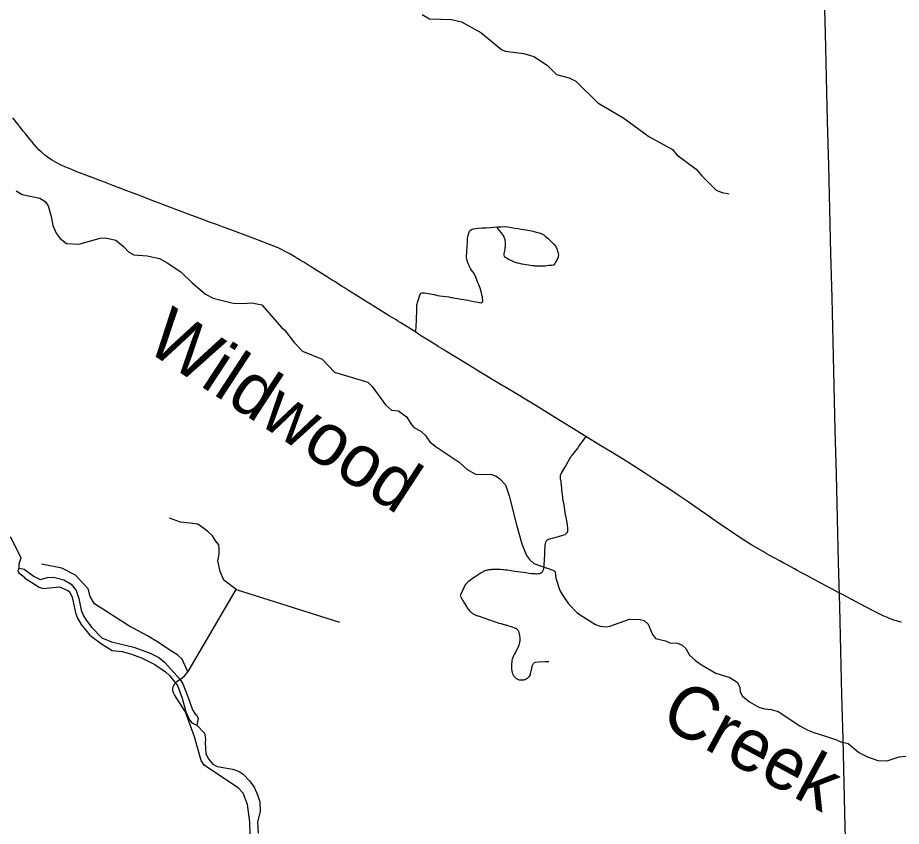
# Model space of a CAD drawing. Extents: x -19 to 366, y -4 to 359.
# Drawn here: x 140.926 to 142.275, y 192.835 to 194.069 of the extents above; entities that cross this region are included whole.
import ezdxf

# ---------------------------------------------------------------- set-up
doc = ezdxf.new("R2010")
doc.units = 0
for name, color, linetype in [('R_ROW', 7, 'Continuous'), ('R_ROW Annot', 7, 'Continuous'), ('R_Striping', 7, 'Continuous'), ('R_Temp Easement', 7, 'Continuous'), ('Sheet Fence', 7, 'Continuous')]:
    doc.layers.add(name, color=color, linetype=linetype)

msp = doc.modelspace()

# ---------------------------------------------------------------- linework, layer by layer
at = {"layer": 'R_ROW'}
for points in [[(141.5338, 193.589), (141.5108, 193.6034), (141.5066, 193.606), (141.5037, 193.6078), (141.4931, 193.6143), (141.4893, 193.6166), (141.4689, 193.6294), (141.4657, 193.6313), (141.4598, 193.635), (141.4564, 193.6372), (141.431, 193.653), (141.425, 193.6568), (141.4216, 193.659), (141.4142, 193.6637), (141.41, 193.6663), (141.4052, 193.6692), (141.3977, 193.674), (141.3895, 193.6791), (141.3827, 193.6834), (141.3772, 193.6868), (141.3739, 193.689), (141.3705, 193.6911), (141.3677, 193.6929), (141.3627, 193.6959), (141.3579, 193.6988), (141.3542, 193.701), (141.3505, 193.7033), (141.3455, 193.7063), (141.3442, 193.707), (141.3414, 193.7086), (141.3397, 193.7096), (141.3239, 193.7177), (141.3106, 193.7231), (141.2988, 193.7277), (141.2879, 193.7318), (141.2841, 193.7331), (141.2772, 193.7357), (141.2555, 193.7438), (141.2471, 193.7469), (141.2388, 193.7499), (141.2308, 193.7529), (141.2174, 193.7578), (141.2113, 193.76), (141.2031, 193.7632), (141.1935, 193.7667), (141.1862, 193.7695), (141.1788, 193.7723), (141.1701, 193.7756), (141.1622, 193.7785), (141.1484, 193.7836), (141.1408, 193.7866), (141.1337, 193.7893), (141.1271, 193.7918), (141.1183, 193.7952), (141.0995, 193.8024), (141.0912, 193.8056), (141.0847, 193.8081), (141.0777, 193.8107), (141.071, 193.8133), (141.0633, 193.8163), (141.056, 193.819), (141.0497, 193.8214), (141.0436, 193.8237), (141.0259, 193.8304), (141.0189, 193.8331), (141.0033, 193.8393), (140.9978, 193.8417), (140.9915, 193.8445), (140.9857, 193.8475), (140.9775, 193.8521), (140.9708, 193.8566), (140.9673, 193.8593), (140.9621, 193.8638), (140.9584, 193.8676), (140.9545, 193.8716), (140.951, 193.8757), (140.9474, 193.88), (140.9423, 193.8862), (140.9381, 193.8913), (140.9342, 193.8961), (140.9311, 193.9001), (140.9284, 193.9035), (140.9259, 193.9067), (140.9185, 193.9166)], [(141.7937, 193.4299), (141.7845, 193.4355), (141.7788, 193.439), (141.754, 193.4543), (141.747, 193.4586), (141.7145, 193.4786), (141.6984, 193.4884), (141.6927, 193.4919), (141.6696, 193.5058), (141.6668, 193.5074), (141.6271, 193.5314), (141.6224, 193.5343), (141.6014, 193.5469), (141.5965, 193.5499), (141.5797, 193.5602), (141.575, 193.5631), (141.5678, 193.5675), (141.5628, 193.5707), (141.5428, 193.5833), (141.5382, 193.5862), (141.5338, 193.589)], [(141.7937, 193.4299), (141.7835, 193.416), (141.7811, 193.4128), (141.773, 193.4024), (141.7715, 193.4004), (141.7708, 193.3996), (141.77, 193.3985), (141.7691, 193.3971), (141.7685, 193.3959), (141.763, 193.3856), (141.7612, 193.3825), (141.756, 193.3738), (141.7555, 193.3727), (141.755, 193.3718), (141.7546, 193.3703), (141.7544, 193.3689), (141.7543, 193.3671), (141.7545, 193.3654), (141.755, 193.3636), (141.7553, 193.3611), (141.7559, 193.3545), (141.7562, 193.3521), (141.7564, 193.3496), (141.7566, 193.3482), (141.7578, 193.3377), (141.758, 193.3357), (141.7586, 193.3322), (141.7592, 193.3289), (141.7622, 193.3105), (141.7628, 193.3072), (141.7648, 193.2946), (141.7654, 193.2907), (141.7655, 193.2895), (141.7657, 193.2869), (141.7655, 193.2851), (141.7645, 193.2832), (141.7639, 193.2825), (141.7613, 193.2801), (141.7578, 193.2789), (141.7511, 193.2766), (141.7478, 193.2757), (141.746, 193.2752), (141.7438, 193.2746), (141.7422, 193.2741), (141.7403, 193.2737), (141.7378, 193.2731), (141.7359, 193.2724), (141.7346, 193.2716), (141.7337, 193.2708), (141.7329, 193.2699), (141.7322, 193.2686), (141.7315, 193.2666), (141.7311, 193.2639), (141.7308, 193.2611), (141.7305, 193.2565), (141.7303, 193.2534), (141.7302, 193.2503), (141.7296, 193.2338), (141.7295, 193.2322), (141.7294, 193.2309), (141.7291, 193.2289), (141.7287, 193.2274), (141.7281, 193.2254), (141.7276, 193.2241), (141.727, 193.2231), (141.7263, 193.2222), (141.7259, 193.2219), (141.7243, 193.2211), (141.7229, 193.2206), (141.7206, 193.2201), (141.7187, 193.22), (141.7175, 193.22), (141.716, 193.2201), (141.7125, 193.2203), (141.7105, 193.2206), (141.7066, 193.221), (141.7018, 193.2217), (141.6899, 193.2233), (141.6852, 193.2239), (141.6738, 193.2258), (141.6722, 193.226), (141.6708, 193.2262), (141.6681, 193.2264), (141.6666, 193.2266), (141.6629, 193.2268), (141.6607, 193.2269), (141.6597, 193.2269), (141.6579, 193.2269), (141.6496, 193.2268), (141.6484, 193.2267), (141.6458, 193.2265), (141.6448, 193.2264), (141.6441, 193.2262), (141.6425, 193.2259), (141.6417, 193.2256), (141.6392, 193.2247), (141.6378, 193.224), (141.636, 193.223), (141.6346, 193.2222), (141.6338, 193.2218)], [(142.1056, 193.2313), (142.1009, 193.2339), (142.0957, 193.2368), (142.0897, 193.24), (142.08, 193.2455), (142.0746, 193.2485), (142.0692, 193.2515), (142.0677, 193.2523), (142.0587, 193.2574), (142.0473, 193.264), (142.0287, 193.2756), (142.0173, 193.2832), (141.9941, 193.2993), (141.9821, 193.3077), (141.97, 193.3162), (141.9498, 193.3301), (141.9348, 193.3402), (141.9227, 193.3484), (141.9118, 193.3555), (141.9, 193.3633), (141.891, 193.3693), (141.8845, 193.3735), (141.8705, 193.3826), (141.8519, 193.3943), (141.8311, 193.407), (141.8166, 193.4159), (141.7937, 193.4299)], [(141.2596, 193.1963), (141.2407, 193.2106), (141.2349, 193.224), (141.2317, 193.24), (141.2336, 193.2509), (141.2336, 193.2586), (141.233, 193.2644), (141.2285, 193.2702), (141.2234, 193.2785), (141.2157, 193.2855), (141.201, 193.2964), (141.1895, 193.2977), (141.1747, 193.299), (141.1575, 193.3054)], [(142.1662, 193.199), (142.1613, 193.2016), (142.1547, 193.2051), (142.1302, 193.2182), (142.1219, 193.2226), (142.1163, 193.2256), (142.112, 193.2279), (142.1056, 193.2313)], [(141.6338, 193.2218), (141.6323, 193.2208), (141.6243, 193.2156), (141.6205, 193.2131), (141.6199, 193.2126), (141.618, 193.2112), (141.6139, 193.2082), (141.6127, 193.2072), (141.6122, 193.2067), (141.6113, 193.2057), (141.6107, 193.205), (141.6099, 193.2039), (141.609, 193.2024), (141.6071, 193.1989), (141.6064, 193.1976), (141.6057, 193.1961), (141.6019, 193.1883), (141.6015, 193.1874)], [(142.2466, 193.1568), (142.2435, 193.1584), (142.2387, 193.1608), (142.2178, 193.1716), (142.2159, 193.1727), (142.2025, 193.1798), (142.1996, 193.1813), (142.1846, 193.1892), (142.1812, 193.191), (142.1709, 193.1965), (142.1662, 193.199)], [(141.1858, 193.071), (141.1878, 193.074), (141.2596, 193.1963), (141.4174, 193.1466)], [(141.6015, 193.1874), (141.6054, 193.1801), (141.6063, 193.1785), (141.6069, 193.1775), (141.6113, 193.1703), (141.6135, 193.1668), (141.6143, 193.1659), (141.6164, 193.1635), (141.617, 193.1629), (141.6175, 193.1623), (141.6183, 193.1617), (141.6207, 193.1599), (141.6217, 193.1593), (141.6224, 193.1589), (141.6233, 193.1585), (141.6248, 193.1578), (141.6282, 193.1564), (141.629, 193.1561), (141.648, 193.1494), (141.6506, 193.1485), (141.6582, 193.146), (141.6609, 193.1452), (141.6643, 193.1443), (141.6664, 193.1437), (141.6674, 193.1435), (141.6703, 193.1427), (141.6717, 193.1423), (141.6755, 193.1411), (141.6796, 193.1398), (141.6812, 193.1393), (141.6834, 193.1385), (141.6858, 193.1376), (141.6864, 193.1373), (141.6868, 193.1372), (141.6874, 193.1367), (141.6889, 193.1354), (141.6894, 193.1348), (141.6902, 193.1337), (141.6907, 193.1326), (141.6912, 193.1307), (141.6917, 193.1289), (141.6922, 193.1262), (141.6925, 193.1251), (141.6927, 193.1231), (141.6928, 193.1219), (141.6926, 193.1172), (141.6925, 193.1168), (141.6923, 193.1155), (141.6919, 193.1133), (141.6914, 193.1117), (141.6903, 193.1089), (141.6901, 193.1083), (141.6891, 193.1064), (141.6857, 193.1), (141.6848, 193.0981), (141.6833, 193.0952), (141.6827, 193.0938), (141.6818, 193.0918), (141.6812, 193.0902), (141.6807, 193.0882), (141.6805, 193.0869), (141.6803, 193.0855), (141.68, 193.083), (141.6799, 193.081), (141.6798, 193.0797), (141.6798, 193.078), (141.68, 193.0762), (141.6801, 193.0742), (141.6805, 193.0723), (141.6811, 193.0699), (141.6814, 193.0686), (141.6822, 193.0668), (141.6828, 193.0656), (141.6832, 193.0649), (141.6844, 193.0633), (141.6855, 193.0621), (141.6863, 193.0614), (141.6874, 193.0605), (141.6885, 193.06), (141.6893, 193.0596), (141.69, 193.0593), (141.6908, 193.0591), (141.6919, 193.0588), (141.6929, 193.0586), (141.6936, 193.0585), (141.6956, 193.0584), (141.6961, 193.0584), (141.6968, 193.0584), (141.6973, 193.0585), (141.6995, 193.0588), (141.7001, 193.059), (141.7008, 193.0592), (141.7016, 193.0595), (141.7028, 193.0601), (141.7035, 193.0605), (141.7043, 193.061), (141.7046, 193.0612), (141.705, 193.0615), (141.7066, 193.0631), (141.7069, 193.0634)], [(142.2728, 193.1473), (142.2684, 193.1484), (142.2656, 193.1492), (142.2582, 193.1518), (142.2541, 193.1535), (142.2489, 193.1558), (142.2466, 193.1568)], [(141.7069, 193.0634), (141.7073, 193.0638), (141.7078, 193.0646), (141.7089, 193.0664), (141.709, 193.0666), (141.7093, 193.0679), (141.7102, 193.0724), (141.7104, 193.0735), (141.7112, 193.077), (141.7115, 193.0782), (141.7122, 193.0808), (141.7127, 193.0818), (141.7132, 193.0827), (141.7135, 193.0834), (141.7145, 193.0843), (141.7152, 193.0849), (141.7154, 193.085), (141.7173, 193.0857), (141.7214, 193.086), (141.7317, 193.0864), (141.7334, 193.0864), (141.737, 193.0865)], [(141.2824, 192.761), (141.2805, 192.842), (141.277, 192.8681), (141.27, 192.8857), (141.2626, 192.8938), (141.2311, 192.9144), (141.2108, 192.9281), (141.2061, 192.9356), (141.1959, 192.9716), (141.1831, 193.0069), (141.1806, 193.0117), (141.1653, 193.0356), (141.1641, 193.0378), (141.1633, 193.0402), (141.1629, 193.0427), (141.163, 193.0452), (141.1634, 193.0477), (141.1643, 193.0501), (141.1655, 193.0523), (141.1671, 193.0542), (141.169, 193.0559), (141.1725, 193.0584), (141.1769, 193.0615), (141.1811, 193.0652), (141.1847, 193.0693), (141.1858, 193.071)]]:
    msp.add_lwpolyline(points, dxfattribs=at)
at = {"layer": 'R_ROW Annot'}
for points in [[(141.5338, 193.589), (141.5345, 193.5992), (141.5346, 193.6004), (141.535, 193.6056), (141.5351, 193.6077), (141.5352, 193.609), (141.5354, 193.6223), (141.5354, 193.629), (141.5354, 193.6303), (141.5358, 193.6318), (141.5364, 193.6341), (141.537, 193.6363), (141.5378, 193.6389), (141.54, 193.6459), (141.5409, 193.648), (141.5434, 193.6492), (141.5471, 193.6494), (141.5619, 193.6468), (141.5669, 193.6454), (141.5708, 193.6445), (141.5845, 193.6431), (141.5877, 193.6423), (141.5901, 193.6419), (141.5942, 193.6413), (141.5979, 193.6408), (141.6032, 193.6398), (141.6074, 193.6391), (141.6131, 193.638), (141.6223, 193.6361), (141.6257, 193.6354), (141.6281, 193.635), (141.6311, 193.6344), (141.6339, 193.634), (141.6362, 193.6358), (141.6355, 193.6434), (141.6353, 193.6444), (141.6344, 193.6491), (141.632, 193.6564), (141.631, 193.6589), (141.63, 193.6613), (141.6295, 193.6627), (141.6287, 193.6645), (141.6276, 193.6675), (141.6254, 193.6734), (141.6246, 193.6756), (141.6237, 193.6774), (141.6233, 193.678), (141.6192, 193.6836), (141.6174, 193.6865), (141.6155, 193.6903), (141.615, 193.6912), (141.6147, 193.6922), (141.614, 193.6939), (141.6125, 193.6982), (141.6121, 193.6994), (141.6117, 193.7007), (141.6114, 193.7032), (141.6113, 193.7049), (141.6113, 193.7058), (141.6117, 193.7104), (141.6119, 193.7132), (141.6122, 193.7194), (141.6126, 193.7267), (141.6129, 193.7308), (141.6134, 193.7356), (141.6137, 193.7368), (141.6147, 193.7401), (141.6161, 193.7433), (141.6175, 193.745), (141.6189, 193.746), (141.6219, 193.7469), (141.6249, 193.7475), (141.6293, 193.7481), (141.635, 193.7484), (141.6415, 193.7487), (141.6479, 193.7492), (141.6531, 193.7494), (141.6585, 193.7498)], [(141.6585, 193.7498), (141.6642, 193.7502), (141.6693, 193.7503), (141.6742, 193.7499), (141.6801, 193.7489), (141.6845, 193.7479), (141.6902, 193.7472), (141.6948, 193.7466), (141.7021, 193.7455), (141.7078, 193.7445), (141.7128, 193.7434), (141.7177, 193.7421), (141.7223, 193.7407), (141.7265, 193.7394), (141.7293, 193.7379), (141.7317, 193.7358), (141.7359, 193.732), (141.7407, 193.7274), (141.7447, 193.7236), (141.7471, 193.7207), (141.7478, 193.7197), (141.7486, 193.7179), (141.7499, 193.7147), (141.7505, 193.713), (141.7512, 193.7101), (141.7516, 193.7075), (141.7513, 193.7052), (141.7511, 193.7038), (141.7498, 193.7003), (141.7474, 193.6961), (141.7461, 193.6941), (141.7446, 193.692), (141.7435, 193.6914), (141.741, 193.6912), (141.7385, 193.691), (141.7365, 193.6908), (141.7342, 193.6905), (141.7321, 193.6902), (141.7292, 193.6899), (141.7263, 193.6898), (141.722, 193.6897), (141.7199, 193.6899), (141.7163, 193.6902), (141.715, 193.6904), (141.7122, 193.6907), (141.7083, 193.6912), (141.7058, 193.6916), (141.7026, 193.6921), (141.6996, 193.6926), (141.6959, 193.6932), (141.6927, 193.6938), (141.6892, 193.6947), (141.6847, 193.6963), (141.6818, 193.6975), (141.6796, 193.6984), (141.6765, 193.6998), (141.6747, 193.7007), (141.6725, 193.7021), (141.671, 193.7031), (141.67, 193.7039), (141.6693, 193.7048), (141.6689, 193.7065), (141.6689, 193.7077), (141.669, 193.7092), (141.6695, 193.7115), (141.6699, 193.7136), (141.6702, 193.7153), (141.6705, 193.7174), (141.6706, 193.7184), (141.6707, 193.7191), (141.6707, 193.7252), (141.6703, 193.7299), (141.6695, 193.7329), (141.6683, 193.7359), (141.665, 193.7409), (141.6614, 193.7451), (141.6598, 193.7471), (141.6589, 193.7484), (141.6585, 193.7498)], [(141.1858, 193.071), (141.1773, 193.09), (141.1705, 193.0964), (141.1567, 193.1048), (141.141, 193.1153), (141.1241, 193.1255), (141.0954, 193.1411), (141.0434, 193.1748), (141.0365, 193.186), (141.0336, 193.1973), (141.014, 193.2183), (140.9935, 193.2292), (140.9622, 193.2349)]]:
    msp.add_lwpolyline(points, dxfattribs=at)
at = {"layer": 'R_Striping'}
msp.add_lwpolyline([(142.2759, 193.1466), (142.2728, 193.1473)], dxfattribs=at)
at = {"layer": 'R_Temp Easement'}
for points in [[(141.5435, 194.0741), (141.5549, 194.0674), (141.5886, 194.0667), (141.6038, 194.0627), (141.6331, 194.0464), (141.6648, 194.0206), (141.6705, 194.018), (141.6989, 194.0146), (141.7141, 194.0099), (141.7347, 193.9968), (141.7489, 193.9826), (141.7682, 193.9772), (141.7781, 193.9723), (141.8118, 193.9394), (141.8514, 193.9156), (141.8896, 193.888), (141.9258, 193.868), (141.9323, 193.8601), (141.9621, 193.8381), (141.9709, 193.8279), (141.9924, 193.8062), (142.0019, 193.8025), (142.0125, 193.8004)], [(140.9233, 193.8051), (140.9328, 193.7992), (140.9597, 193.7936), (140.9678, 193.7888), (140.9724, 193.782), (140.9772, 193.7658), (140.9797, 193.7518), (140.9848, 193.7405), (140.9907, 193.7322), (141.0002, 193.7244), (141.0195, 193.7236), (141.0519, 193.7325), (141.0602, 193.7334), (141.0757, 193.7295), (141.0876, 193.7198), (141.0949, 193.712)], [(141.0949, 193.712), (141.1033, 193.7072), (141.1234, 193.7057), (141.1423, 193.7014), (141.1542, 193.6952), (141.1752, 193.6811), (141.1925, 193.6647), (141.2128, 193.6472), (141.2243, 193.641), (141.255, 193.6335), (141.269, 193.633), (141.2833, 193.634), (141.2985, 193.6308), (141.329, 193.5965), (141.3336, 193.5927), (141.3479, 193.5736), (141.3606, 193.5602), (141.391, 193.5478), (141.4095, 193.528), (141.4608, 193.5129), (141.4673, 193.5062), (141.4875, 193.4781), (141.497, 193.4703), (141.5076, 193.469), (141.5199, 193.4601), (141.5281, 193.4469), (141.5311, 193.4436), (141.5414, 193.438), (141.5487, 193.4317), (141.5553, 193.422), (141.5634, 193.4153), (141.6001, 193.3908), (141.6124, 193.3797), (141.625, 193.3723), (141.6386, 193.3718), (141.6484, 193.3727), (141.6568, 193.3694), (141.6621, 193.3653), (141.671, 193.356), (141.6765, 193.3394), (141.6879, 193.2952), (141.6956, 193.2661), (141.7031, 193.2484), (141.7073, 193.2424), (141.7139, 193.2361), (141.7447, 193.2252), (141.7466, 193.2233), (141.7479, 193.2135), (141.7539, 193.195), (141.7582, 193.1871), (141.7671, 193.1744), (141.7806, 193.1605), (141.8085, 193.1428), (141.8157, 193.1403), (141.8248, 193.1397), (141.8304, 193.1405), (141.8601, 193.1513), (141.8763, 193.1508), (141.8828, 193.149), (141.8889, 193.1434), (141.8953, 193.128)], [(140.9143, 193.2774), (140.9299, 193.2475), (140.9307, 193.2441), (140.9277, 193.2353), (140.9277, 193.2289), (140.9262, 193.2251)], [(140.9277, 193.2289), (140.9357, 193.2274), (140.9512, 193.2161), (140.9603, 193.2119), (140.9716, 193.215), (140.9807, 193.2151), (140.9966, 193.2113), (141.0076, 193.2045), (141.0152, 193.1951), (141.0194, 193.1826), (141.0229, 193.1648), (141.0263, 193.1564), (141.0305, 193.1496), (141.0389, 193.1386), (141.0544, 193.1228), (141.0692, 193.1164), (141.1033, 193.1082), (141.1283, 193.0995), (141.1412, 193.0924), (141.1503, 193.0856), (141.1742, 193.0591), (141.178, 193.0527), (141.186, 193.0315), (141.1929, 193.0129), (141.1975, 193.0057), (141.199, 193.005), (141.2017, 192.9997), (141.1994, 192.9894)], [(140.9262, 193.2251), (140.927, 193.2224), (140.9361, 193.2153), (140.9361, 193.2141), (140.9585, 193.1998), (140.9649, 193.1979), (140.9895, 193.2003), (141.0023, 193.195), (141.0054, 193.1924), (141.0092, 193.1848), (141.0142, 193.1606), (141.0173, 193.1526), (141.0226, 193.1428), (141.0363, 193.1265), (141.0537, 193.1133), (141.0704, 193.1035), (141.0855, 193.1016), (141.0984, 193.0983), (141.1151, 193.0919), (141.1355, 193.0821), (141.1518, 193.0708), (141.1575, 193.0651), (141.1701, 193.05), (141.177, 193.0307), (141.1827, 193.0098), (141.1881, 192.9973), (141.1919, 192.9928), (141.1994, 192.9894), (141.2112, 192.9773), (141.2128, 192.9682), (141.212, 192.9625), (141.2132, 192.9454), (141.2171, 192.9379), (141.2239, 192.9296), (141.2307, 192.9262), (141.2542, 192.9221), (141.264, 192.9187), (141.2701, 192.9146), (141.28, 192.9044), (141.2868, 192.8945), (141.2922, 192.8828), (141.2956, 192.8725), (141.2964, 192.8578), (141.2923, 192.8418), (141.2932, 192.8247)], [(141.8953, 193.128), (141.8999, 193.1216), (141.9151, 193.1181), (141.9219, 193.1151), (141.9337, 193.1146), (141.9409, 193.1113), (141.9463, 193.1064), (141.9521, 193.0963), (141.9613, 193.0877), (141.9701, 193.0814), (141.9923, 193.0689), (142.0135, 193.0621), (142.0246, 193.055), (142.0285, 193.0475), (142.0294, 193.0403), (142.0329, 193.0335), (142.0433, 193.025), (142.0578, 193.0169), (142.0665, 193.0144), (142.0764, 193.0134), (142.0874, 193.0102), (142.1206, 192.9884), (142.1317, 192.9821), (142.1416, 192.9781), (142.1598, 192.9727), (142.1766, 192.9669), (142.1834, 192.9636)], [(142.2821, 192.9413), (142.2717, 192.9405), (142.2535, 192.9344), (142.2399, 192.9349), (142.2243, 192.9407), (142.2102, 192.9476), (142.1944, 192.9609), (142.1834, 192.9636)]]:
    msp.add_lwpolyline(points, dxfattribs=at)
at = {"layer": 'Sheet Fence'}
for points in [[(146.7783, 1.697), (146.5788, 10.3131), (146.3785, 18.9294), (146.1776, 27.5458), (145.9759, 36.1624), (145.7736, 44.7791), (145.5705, 53.396), (145.3668, 62.013), (145.1624, 70.6301), (144.9572, 79.2474), (144.7514, 87.8648), (144.5449, 96.4823), (144.3377, 105.1), (144.1299, 113.7179), (143.9213, 122.3359), (143.712, 130.954), (143.5021, 139.5723), (143.2915, 148.1907), (143.0802, 156.8092), (142.8682, 165.4279), (142.6555, 174.0468), (142.4422, 182.6658), (142.2282, 191.2849), (142.0135, 199.9042), (141.7981, 208.5236), (141.582, 217.1432), (141.3653, 225.7629), (141.1479, 234.3828), (140.9298, 243.0028), (140.711, 251.623), (140.4916, 260.2433), (140.2715, 268.8638), (140.0508, 277.4844), (139.8293, 286.1051), (139.6072, 294.726), (139.3845, 303.3471), (139.161, 311.9683), (138.937, 320.5896), (138.7122, 329.2111), (138.4868, 337.8328), (138.2607, 346.4546)], [(0, 189.5162), (7.1121, 189.5206), (14.2243, 189.5339), (21.3364, 189.556), (28.4484, 189.5869), (35.5605, 189.6267), (42.6725, 189.6754), (49.7844, 189.7329), (56.8962, 189.7992), (64.0079, 189.8744), (71.1196, 189.9584), (78.2311, 190.0512), (85.3425, 190.1529), (92.4538, 190.2635), (99.5649, 190.3829), (106.6759, 190.5111), (113.7867, 190.6482), (120.8974, 190.7941), (128.0078, 190.9489), (135.1181, 191.1125), (142.2282, 191.2849), (149.338, 191.4662), (156.4476, 191.6563), (163.5569, 191.8553), (170.666, 192.0631), (177.7749, 192.2798), (184.8835, 192.5053), (191.9917, 192.7396), (199.0997, 192.9828), (206.2074, 193.2348), (213.3147, 193.4956), (220.4218, 193.7653), (227.5285, 194.0438), (234.6348, 194.3312), (241.7408, 194.6274), (248.8464, 194.9324), (255.9516, 195.2463), (263.0564, 195.569), (270.1608, 195.9005), (277.2648, 196.2409), (284.3683, 196.5901), (291.4715, 196.9481), (298.5741, 197.315), (305.6763, 197.6907), (312.7781, 198.0753), (319.8793, 198.4686), (326.9801, 198.8708), (334.0804, 199.2818), (341.1801, 199.7017)]]:
    msp.add_spline(points, degree=3, dxfattribs=at)

# ---------------------------------------------------------------- texts
at = {"layer": 'R_Temp Easement'}
for s, rotation, p in [('Wildwood', 326.851, (141.1181, 193.5636)), ('Creek', 331.5581, (141.9039, 192.9915))]:
    msp.add_text(s, height=0.08, rotation=rotation, dxfattribs=at).set_placement(p)

doc.saveas('drawing.dxf')
